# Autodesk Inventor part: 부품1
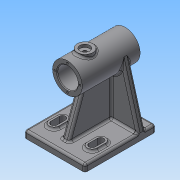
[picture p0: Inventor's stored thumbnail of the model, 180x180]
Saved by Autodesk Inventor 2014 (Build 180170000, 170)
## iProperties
Created: 2019-10
Part Number: 부품1
Material: 일반
Document SubType Name: Modeling
Designer: NET
Density: 1 g/cm^3
Appearance: 기본값
Author: NET
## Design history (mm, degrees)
sketch "스케치1"
  geometry: C1 r 21 at (0, 0); 1 further point
  constraints: 1 centre point, 1 coincident
  dimensions: "d0" = 42 diameter of C1
extrude "돌출1" new body sketch "스케치1" distance "d1" = 82; taper "d2" = 0 deg
sketch "스케치2"
  geometry: L1 (0, 0)-(0, 14.5); L2 (0, 21)-(0, -21) reference; L3 (62, 14.5)-(62, 11.5); L4 (62, 11.5)-(82, 11.5); L5 (82, -21)-(82, 21) reference; L6 (82, 0)-(0, 0); L7 (0, 0)-(0, 14.5); L8 (62, 14.5)-(0, 14.5)
  constraints: 12 end point, 2 parallel, 2 perpendicular, 2 point on line, 1 collinear, 1 midpoint
  dimensions: "d3" = 62 distance of L3.start L1.end; "d4" = 29 diameter of L8 L6; "d5" = 23 diameter of L4 L6
revolve "회전1" sketch "스케치2" stored, may be unused: angle "d6" = 90 deg
node "작업 평면1"
sketch "스케치3"
  geometry: L1 (21, 82)-(-21, 82) reference; L2 (-43, 82)-(43, 82); L3 (43, 82)-(43, -18); L4 (43, -18)-(-43, -18); L5 (-43, -18)-(-43, 82); 2 further points
  constraints: 8 end point, 2 midpoint, 2 parallel, 1 horizontal, 1 perpendicular
  dimensions: "d8" = 86 distance of L2.start L2.end; "d9" = 100 distance of L4.end L2.start
extrude "돌출2" join sketch "스케치3" distance "d10" = 10; taper "d11" = 0 deg
sketch "스케치4"
  geometry: L1 (-43, 82)-(-43, -18) reference; L2 (-43, -18)-(43, -18) reference; L3 (-27, 20)-(-27, 8); L4 (-34, 20)-(-34, 8); L5 (-20, 8)-(-20, 20); L6 (27, 20)-(27, 8); L7 (34, 20)-(34, 8); L8 (20, 8)-(20, 20); A1 r 7 centre (-27, 20) between (-20, 20) and (-34, 20); A2 r 7 centre (-27, 8) between (-34, 8) and (-20, 8); A3 r 7 centre (27, 20) between (34, 20) and (20, 20); A4 r 7 centre (27, 8) between (20, 8) and (34, 8); 3 further points
  constraints: 16 end point, 8 point on circle, 8 tangent, 5 parallel, 4 centre point, 2 midpoint, 1 equal radius
  dimensions: "d12" = 12 distance of L7.start L7.end; "d13" = 7 radius of A3; "d14" = 54 distance of L6.end L3.end; "d15" = 26 distance from line of L2 L6.end; "d16" = 26 distance from line of L2 L3.end; "d17" = 27 horizontal distance of L3.end point (0, 0)
extrude "돌출3" join sketch "스케치4" distance "d18" = 3; taper "d19" = 0 deg
sketch "스케치5"
  geometry: L1 (-34, 20)-(-34, 8) reference; L2 (34, 20)-(34, 8) reference; L3 (-20, 20)-(-20, 8) reference; L4 (-34, 8)-(-34, 20) reference; L5 (20, 8)-(20, 20) reference; L6 (34, 20)-(34, 8) reference; L7 (43, 82)-(-43, 82) reference; L8 (-43, 82)-(-43, -18) reference; L9 (-43, -18)-(43, -18) reference; L10 (43, -18)-(43, 82) reference; L11 (-27, 20)-(-27, 8); L12 (-31.5, 20)-(-31.5, 8); L13 (-22.5, 8)-(-22.5, 20); L14 (27, 20)-(27, 8); L15 (22.5, 20)-(22.5, 8); L16 (31.5, 8)-(31.5, 20); A1 r 7 centre (27, 20) between (34, 20) and (20, 20) reference; A2 r 7 centre (27, 8) between (20, 8) and (34, 8) reference; A3 r 7 centre (-27, 20) between (-20, 20) and (-34, 20) reference; A4 r 7 centre (-27, 8) between (-34, 8) and (-20, 8) reference; A5 r 7 centre (27, 8) between (20, 8) and (34, 8) reference; A6 r 7 centre (27, 20) between (34, 20) and (20, 20) reference; A7 r 4.5 centre (-27, 20) between (-22.5, 20) and (-31.5, 20); A8 r 4.5 centre (-27, 8) between (-31.5, 8) and (-22.5, 8); A9 r 4.5 centre (27, 20) between (31.5, 20) and (22.5, 20); A10 r 4.5 centre (27, 8) between (22.5, 8) and (31.5, 8); 3 further points
  constraints: 16 end point, 8 point on circle, 8 tangent, 4 centre point, 4 parallel, 2 midpoint, 1 equal radius
  dimensions: "d20" = 4.5 radius of A9
extrude "돌출4" cut sketch "스케치5" stored distance "d21" = 3; taper "d22" = 0 deg
sketch "스케치6"
  geometry: L1 (82, -76)-(-18, -76) reference; L2 (-3, -76)-(18, -18.303); L3 (18, -18.303)-(67, -18.303); L4 (0, -21)-(82, -21) reference; L5 (67, -18.303)-(67, -76); L6 (-3, -76)-(67, -76); L7 (82, -86)-(82, -76) reference; 1 further point
  constraints: 8 end point, 2 point on line, 1 collinear, 1 parallel, 1 perpendicular
  dimensions: "d23" = 15 distance of L1.end L2.start; "d24" = 70 deg angle of L1 L2; "d25" = 15 distance between parallel lines of L5 L7; "d26" = 49 distance of L2.end L3.end
extrude "돌출5" join sketch "스케치6" distance "d27" = 5; taper "d29" = 0 deg; dims "d28" = 5, "d30" = 0
sketch "스케치7"
  geometry: L1 (5, 76)-(5, 20.396) reference; L2 (-5, 20.396)-(-5, 76) reference; L3 (-43, 76)-(43, 76) reference; L4 (-43, 76)-(-20.228, -5.642); L5 (43, 76)-(20.228, -5.642); A1 r 21 centre (0, 0) between (-5, 20.396) and (5, 20.396) reference
  constraints: 4 end point, 2 point on circle, 2 tangent
extrude "돌출6" join sketch "스케치7" distance "d31" = 10; taper "d32" = 0 deg
sketch "스케치8"
  geometry: C1 r 11.5 at (0, 0) reference; 1 further point
  constraints: 1 vertical alignment
  dimensions: "d33" = 18 distance of point (0, -18) C1.centre
hole "구멍1" sketch "스케치8" at (0, -18) diameter "d34" = 2.459; stored, may be unused: countersink angle "d38" = 90 deg, drill point angle "d40" = 118 deg; dims "d35" = 8, "d36" = 4, "d37" = 2, "d39" = 10
node "작업 평면2"
node "작업 평면3"
sketch "스케치10"
  geometry: L1 (-21, 0)-(21, 0) reference; C1 r 11 at (0, 25); 1 further point
  constraints: 1 centre point, 1 vertical alignment
  dimensions: "d46" = 25 distance from line of C1.centre L1; "d47" = 22 diameter of C1
extrude "돌출7" join sketch "스케치10" stored distance "d48" = 10; taper "d49" = 0 deg
sketch "스케치11"
  geometry: C1 r 7 at (0, -0.338); 4 further points; 1 other entity
  constraints: 1 centre point, 1 coincident, 1 other
  dimensions: "d50" = 14 diameter of C1
extrude "돌출8" cut sketch "스케치11" distance "d51" = 4; taper "d52" = 0 deg
hole "구멍2" diameter "d55" = 4.917; stored, may be unused: countersink angle "d59" = 90 deg, drill point angle "d61" = 118 deg; dims "d53" = 10, "d54" = 10, "d56" = 15, "d57" = 4, "d58" = 2, "d60" = 15
sketch "스케치12"
  geometry: L1 (43, 67)-(43, 82) reference; L2 (43, 82)-(-43, 82) reference; 2 further points
  constraints: 1 other
  dimensions: "d62" = 43 distance from line of L1 point (0, 75); "d63" = 7 distance from line of L2 point (0, 75)
feature "엠보싱1" sketch "스케치12" dims "d2" = 0, "d8" = 86, "d9" = 100, "d64" = 0.5, "d65" = 0
fillet "모깎기15" dims "d80" = 3
fillet "모깎기16" dims "d81" = 3
fillet "모깎기20" dims "d85" = 3
chamfer "모따기1" distance "d86" = 1; stored, may be unused: second distance "d87" = 2, angle "d88" = 45 deg
fillet "모깎기31" dims "d99" = 3
fillet "모깎기34" dims "d102" = 3
fillet "모깎기35" dims "d103" = 3
fillet "모깎기36" dims "d104" = 3
node "솔리드1"
pattern_circular "원형 패턴1" dims angle "d42" = 360 deg
mirror "대칭1"
node "투영된 루프1"
other parameters: "d7" = -86
